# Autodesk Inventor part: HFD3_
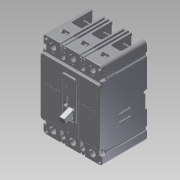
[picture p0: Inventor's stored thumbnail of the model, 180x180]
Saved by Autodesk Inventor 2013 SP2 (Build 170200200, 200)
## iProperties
Created: 2014-08
Part Number: HFD3_
Material: Generic
Document SubType Name: Modeling
Designer: DM/JS
Density: 1 g/cm^3
Description: TYPE HFD THERMAL MAGNETIC CIRCUIT BREAKERS THREE POLE, SERIES C
Translation Standard: STEP AP214IS
FileName: Y:\ECO-062745\WIP\New\FD3_.stp
PreProcessor: Autodesk Inventor 2012
PostProcessor: Build: 219, Release: 2012 SP2 - Date: Fri 04/27/2012
Sent Units: inch
Uncertainty: 0.00039370078740199997
MXEDIT: false
MXINVTNRV: INV Versioned Component|HFD3_|003.0
Author: DM/JS
Revision Number: 003
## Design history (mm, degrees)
node "HFD3_"
node "L1"
node "L2"
node "L3"
node "T1"
node "T2"
node "T3"
body "Solid1"
node "Base1"
